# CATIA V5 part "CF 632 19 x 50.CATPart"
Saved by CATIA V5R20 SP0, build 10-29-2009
Part number: CF 632 19 x 50
Definition: NONE
Nomenclature: CF 632 19 x 50
Source: Unknown
Description: CF 632 19 x 50
Bounding box of the stored display mesh (mm): x -13 to 37, y -17 to 17, z -17 to 17
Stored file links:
  C:\Users\Utente\Desktop\IO LAVORO\3D X SITO CF\X SITO\CF 632\CF 632 19 x 50.CATPart
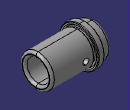
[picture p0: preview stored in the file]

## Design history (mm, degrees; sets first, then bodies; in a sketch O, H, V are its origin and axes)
Body1 "CF 632 19 x 50" (main body)
  Solid1: solid without history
